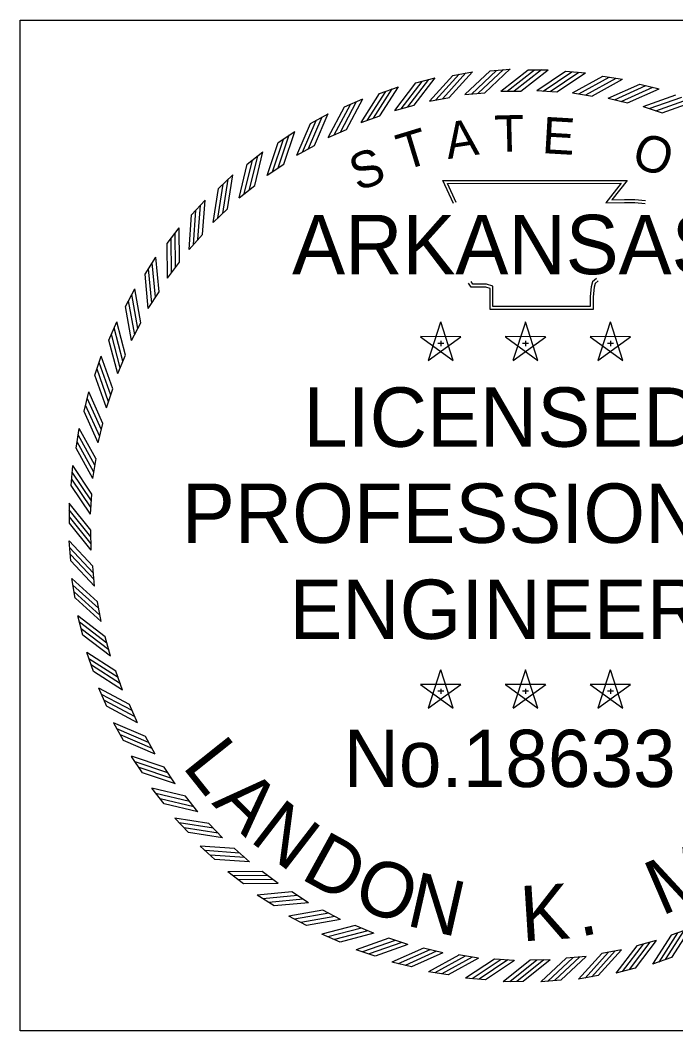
# Model space of a CAD drawing. Extents: x 0 to 1228740, y 0 to 152440.
# Drawn here: x 30.673 to 32.457, y 22.685 to 25.435 of the extents above; entities that cross this region are included whole.
import ezdxf

# ---------------------------------------------------------------- set-up
doc = ezdxf.new("R2010")
doc.units = 0
doc.layers.add('R_No Plot', color=7, linetype='Continuous')
doc.layers.add('STAMP_LKM', color=7, linetype='Continuous')

msp = doc.modelspace()

# ---------------------------------------------------------------- linework, layer by layer
at = {"layer": 'R_No Plot'}
msp.add_lwpolyline([(30.6731, 25.4352), (33.4231, 25.4352), (33.4231, 22.6852), (30.6731, 22.6852)], close=True, dxfattribs=at)
at = {"layer": 'STAMP_LKM'}
for p, q in [((31.952, 25.2973), (32.0062, 25.3023)), ((32.055, 25.3004), (32.1094, 25.3004)), ((31.7497, 25.2646), (31.8023, 25.2785)), ((31.8501, 25.2851), (31.9037, 25.2946)), ((32.1569, 25.2963), (32.2112, 25.2923)), ((32.2586, 25.2831), (32.3124, 25.2746)), ((31.6512, 25.2359), (31.7025, 25.254)), ((32.3589, 25.2615), (32.4118, 25.2486)), ((31.5555, 25.1991), (31.6051, 25.2214)), ((31.7871, 25.2152), (31.8408, 25.2247)), ((31.8834, 25.2329), (31.9377, 25.2379)), ((31.9808, 25.2425), (32.0353, 25.2425)), ((32.0786, 25.244), (32.133, 25.24)), ((32.1763, 25.2374), (32.2301, 25.2289)), ((32.2731, 25.2228), (32.326, 25.2099)), ((31.6926, 25.1897), (31.7453, 25.2036)), ((32.3683, 25.2003), (32.42, 25.183)), ((31.4631, 25.1545), (31.5107, 25.1808)), ((31.6005, 25.1565), (31.6519, 25.1747)), ((31.5115, 25.1158), (31.5612, 25.1382)), ((31.3747, 25.1024), (31.42, 25.1326)), ((31.4262, 25.0679), (31.4739, 25.0943)), ((31.291, 25.0433), (31.3336, 25.0771)), ((31.3451, 25.0131), (31.3904, 25.0433)), ((31.2124, 24.9774), (31.2521, 25.0146)), ((31.2688, 24.9518), (31.3115, 24.9857)), ((31.1395, 24.9052), (31.176, 24.9456)), ((31.1978, 24.8844), (31.2376, 24.9217)), ((31.0728, 24.8273), (31.1058, 24.8706)), ((31.1327, 24.8113), (31.1692, 24.8518)), ((31.0128, 24.7442), (31.0421, 24.79)), ((31.0738, 24.7332), (31.1068, 24.7765)), ((30.9598, 24.6563), (30.9853, 24.7044)), ((31.0215, 24.6504), (31.0509, 24.6963)), ((30.9143, 24.5644), (30.9357, 24.6144)), ((31.8172, 24.6139), (31.7832, 24.5095)), ((31.8512, 24.5095), (31.8173, 24.614)), ((32.048, 24.6139), (32.014, 24.5095)), ((32.0819, 24.5095), (32.0481, 24.614)), ((32.2788, 24.6139), (32.2448, 24.5095)), ((32.3127, 24.5095), (32.2789, 24.614)), ((30.9763, 24.5636), (31.0018, 24.6118)), ((31.8721, 24.574), (31.7623, 24.5741)), ((31.7624, 24.574), (31.8512, 24.5094)), ((31.7833, 24.5095), (31.8723, 24.574)), ((31.8174, 24.5623), (31.8174, 24.5486)), ((32.1029, 24.574), (31.9931, 24.5741)), ((31.9932, 24.574), (32.082, 24.5094)), ((32.0141, 24.5095), (32.103, 24.574)), ((32.0481, 24.5623), (32.0481, 24.5486)), ((32.3337, 24.574), (32.2238, 24.5741)), ((32.2239, 24.574), (32.3127, 24.5094)), ((32.2449, 24.5095), (32.3338, 24.574)), ((32.2789, 24.5623), (32.2789, 24.5486)), ((31.8094, 24.5565), (31.8258, 24.5565)), ((32.0402, 24.5565), (32.0565, 24.5565)), ((32.271, 24.5565), (32.2873, 24.5565)), ((30.8766, 24.4691), (30.8937, 24.5207)), ((30.9384, 24.4734), (30.9598, 24.5235)), ((30.8468, 24.3709), (30.8597, 24.4238)), ((30.908, 24.3803), (30.9253, 24.4321)), ((30.8855, 24.2851), (30.8984, 24.3381)), ((30.8252, 24.2706), (30.8337, 24.3244)), ((30.8709, 24.1883), (30.8794, 24.2422)), ((30.812, 24.1689), (30.816, 24.2232)), ((30.8643, 24.0906), (30.8683, 24.145)), ((30.8073, 24.0665), (30.8068, 24.1209)), ((30.8658, 23.9928), (30.8653, 24.0473)), ((30.811, 23.964), (30.806, 24.0182)), ((30.8754, 23.8954), (30.8704, 23.9497)), ((30.8231, 23.8622), (30.8137, 23.9157)), ((30.8931, 23.7991), (30.8836, 23.8528)), ((30.8437, 23.7617), (30.8298, 23.8143)), ((30.9186, 23.7046), (30.9047, 23.7573)), ((30.8724, 23.6632), (30.8543, 23.7145)), ((30.9518, 23.6125), (30.9336, 23.664)), ((31.8172, 23.6676), (31.7832, 23.5632)), ((31.8512, 23.5633), (31.8173, 23.6678)), ((32.048, 23.6676), (32.014, 23.5632)), ((32.0819, 23.5633), (32.0481, 23.6678)), ((32.2788, 23.6676), (32.2448, 23.5632)), ((32.3127, 23.5633), (32.2789, 23.6678)), ((31.8721, 23.6278), (31.7623, 23.6279)), ((31.7624, 23.6278), (31.8512, 23.5631)), ((31.7833, 23.5633), (31.8723, 23.6277)), ((32.1029, 23.6278), (31.9931, 23.6279)), ((31.9932, 23.6278), (32.082, 23.5631)), ((32.0141, 23.5633), (32.103, 23.6277)), ((32.3337, 23.6278), (32.2238, 23.6279)), ((32.2239, 23.6278), (32.3127, 23.5631)), ((32.2449, 23.5633), (32.3338, 23.6277)), ((30.9092, 23.5675), (30.8869, 23.6171)), ((31.8094, 23.6102), (31.8258, 23.6102)), ((31.8174, 23.6161), (31.8174, 23.6023)), ((32.0402, 23.6102), (32.0565, 23.6102)), ((32.0481, 23.6161), (32.0481, 23.6023)), ((32.271, 23.6102), (32.2873, 23.6102)), ((32.2789, 23.6161), (32.2789, 23.6023)), ((30.9925, 23.5235), (30.9701, 23.5733)), ((30.9538, 23.4751), (30.9275, 23.5227)), ((31.0404, 23.4382), (31.014, 23.4859)), ((31.0059, 23.3868), (30.9757, 23.432)), ((31.0952, 23.3571), (31.065, 23.4025)), ((31.065, 23.303), (31.0312, 23.3456)), ((31.1565, 23.2808), (31.1226, 23.3235)), ((31.1309, 23.2244), (31.0937, 23.2641)), ((31.2239, 23.2098), (31.1866, 23.2496)), ((31.2031, 23.1515), (31.1627, 23.188)), ((31.297, 23.1447), (31.2565, 23.1812)), ((31.281, 23.0848), (31.2377, 23.1178)), ((31.3751, 23.0858), (31.3318, 23.1189)), ((31.3641, 23.0248), (31.3183, 23.0541)), ((31.4579, 23.0335), (31.412, 23.0629)), ((31.452, 22.9719), (31.4039, 22.9973)), ((31.5447, 22.9883), (31.4965, 23.0138)), ((31.6349, 22.9504), (31.5848, 22.9718)), ((32.4958, 22.9638), (32.4443, 22.9456)), ((31.5439, 22.9263), (31.4939, 22.9477)), ((31.728, 22.92), (31.6762, 22.9373)), ((31.8232, 22.8975), (31.7702, 22.9104)), ((32.4037, 22.9306), (32.3509, 22.9167)), ((31.6392, 22.8886), (31.5876, 22.9058)), ((31.92, 22.8829), (31.8661, 22.8914)), ((32.0176, 22.8763), (31.9633, 22.8803)), ((32.2129, 22.8875), (32.1586, 22.8825)), ((32.3092, 22.9051), (32.2555, 22.8956)), ((32.4451, 22.8845), (32.3938, 22.8663)), ((31.7374, 22.8588), (31.6845, 22.8717)), ((32.1155, 22.8779), (32.061, 22.8774)), ((32.3466, 22.8557), (32.294, 22.8419)), ((31.8376, 22.8373), (31.7839, 22.8457)), ((31.9394, 22.824), (31.8851, 22.828)), ((32.2461, 22.8352), (32.1925, 22.8257)), ((32.0418, 22.8193), (31.9874, 22.8188)), ((32.1443, 22.823), (32.0901, 22.818))]:
    msp.add_line(p, q, dxfattribs=at)
for points in [[(31.9195, 25.2364), (31.9881, 25.3009)], [(31.9376, 25.2379), (32.0062, 25.3024)], [(31.9807, 25.2424), (32.0549, 25.3003)], [(31.9982, 25.2422), (32.0724, 25.3001)], [(32.0171, 25.2427), (32.0913, 25.3006)], [(32.0352, 25.2425), (32.1095, 25.3004)], [(31.7277, 25.1992), (31.7847, 25.2741)], [(31.7452, 25.2036), (31.8023, 25.2785)], [(31.787, 25.2152), (31.8501, 25.2851)], [(31.8043, 25.2181), (31.8673, 25.288)], [(31.8228, 25.2218), (31.8859, 25.2917)], [(31.8407, 25.2247), (31.9038, 25.2946)], [(31.8833, 25.2328), (31.9519, 25.2973)], [(31.9007, 25.2342), (31.9694, 25.2987)], [(32.0785, 25.2439), (32.1568, 25.2962)], [(32.096, 25.2425), (32.1743, 25.2948)], [(32.1149, 25.2415), (32.1932, 25.2938)], [(32.1329, 25.24), (32.2112, 25.2923)], [(32.1762, 25.2374), (32.2585, 25.283)], [(32.1935, 25.2345), (32.2758, 25.2801)], [(32.2122, 25.232), (32.2945, 25.2776)], [(32.2301, 25.229), (32.3124, 25.2746)], [(31.6347, 25.1688), (31.6854, 25.2482)], [(31.6519, 25.1747), (31.7025, 25.254)], [(31.6925, 25.1897), (31.7496, 25.2645)], [(31.7095, 25.194), (31.7666, 25.2688)], [(32.273, 25.2228), (32.3588, 25.2615)], [(32.29, 25.2185), (32.3758, 25.2572)], [(32.3084, 25.2144), (32.3942, 25.2531)], [(32.326, 25.21), (32.4118, 25.2487)], [(31.5612, 25.1382), (31.6051, 25.2214)], [(31.6005, 25.1564), (31.6512, 25.2358)], [(31.617, 25.1621), (31.6677, 25.2415)], [(32.3682, 25.2002), (32.4569, 25.2317)], [(32.3848, 25.1946), (32.4735, 25.226)], [(32.4028, 25.189), (32.4916, 25.2205)], [(31.5115, 25.1157), (31.5554, 25.199)], [(31.5275, 25.1228), (31.5715, 25.206)], [(31.5446, 25.1309), (31.5885, 25.2141)], [(32.42, 25.1831), (32.5087, 25.2146)], [(31.4415, 25.0761), (31.4785, 25.1627)], [(31.4579, 25.0857), (31.4948, 25.1723)], [(31.4738, 25.0943), (31.5107, 25.1809)], [(31.4261, 25.0678), (31.4631, 25.1544)], [(31.3597, 25.0226), (31.3894, 25.1119)], [(31.3752, 25.0334), (31.4049, 25.1228)], [(31.3904, 25.0433), (31.42, 25.1327)], [(31.345, 25.013), (31.3747, 25.1024)], [(31.2826, 24.9624), (31.3048, 25.0539)], [(31.2971, 24.9745), (31.3193, 25.066)], [(31.3114, 24.9857), (31.3336, 25.0771)], [(31.2688, 24.9517), (31.2909, 25.0432)], [(31.2242, 24.9094), (31.2387, 25.0024)], [(31.2375, 24.9217), (31.2521, 25.0147)], [(31.8523, 24.9362), (31.8233, 24.999), (32.3251, 24.9993), (32.2832, 24.9466), (32.3172, 24.9471), (32.3457, 24.9474), (32.3742, 24.9443)], [(31.1978, 24.8843), (31.2123, 24.9773)], [(31.2107, 24.8961), (31.2252, 24.9892)], [(31.8595, 24.9395), (31.8357, 24.9911), (32.3086, 24.9914), (32.2665, 24.9385), (32.3173, 24.9391), (32.3453, 24.9395), (32.3733, 24.9364)], [(31.1691, 24.8518), (31.176, 24.9457)], [(31.1445, 24.8241), (31.1513, 24.918)], [(31.1569, 24.8384), (31.1637, 24.9323)], [(31.1326, 24.8113), (31.1395, 24.9051)], [(31.1068, 24.7765), (31.1058, 24.8706)], [(31.0845, 24.7469), (31.0835, 24.841)], [(31.0956, 24.7622), (31.0947, 24.8563)], [(31.0738, 24.7331), (31.0728, 24.8272)], [(31.0508, 24.6963), (31.0421, 24.79)], [(31.0311, 24.665), (31.0224, 24.7587)], [(31.0409, 24.6811), (31.0322, 24.7749)], [(31.0215, 24.6503), (31.0128, 24.7441)], [(32.246, 24.7259), (32.2375, 24.719), (32.2346, 24.7086), (32.2318, 24.6825), (32.2318, 24.6479), (31.9517, 24.6479), (31.9517, 24.6947), (31.9517, 24.7051), (31.9403, 24.7086), (31.9005, 24.7086), (31.8934, 24.7194)], [(32.241, 24.7321), (32.2305, 24.7235), (32.2268, 24.71), (32.2238, 24.683), (32.2238, 24.6558), (31.9596, 24.6558), (31.9596, 24.6947), (31.9596, 24.711), (31.9415, 24.7165), (31.9047, 24.7165), (31.9, 24.7237)], [(31.0017, 24.6118), (30.9853, 24.7045)], [(30.9846, 24.5789), (30.9682, 24.6716)], [(30.9931, 24.5958), (30.9766, 24.6885)], [(30.9763, 24.5635), (30.9598, 24.6562)], [(30.9597, 24.5235), (30.9357, 24.6145)], [(30.9525, 24.5069), (30.9284, 24.5979)], [(30.9384, 24.4733), (30.9143, 24.5643)], [(30.9454, 24.4893), (30.9214, 24.5804)], [(30.9193, 24.4149), (30.8878, 24.5036)], [(30.9252, 24.432), (30.8937, 24.5207)], [(30.9137, 24.3968), (30.8823, 24.4855)], [(30.908, 24.3802), (30.8766, 24.469)], [(30.8983, 24.338), (30.8596, 24.4238)], [(30.8939, 24.3204), (30.8552, 24.4063)], [(30.8855, 24.285), (30.8468, 24.3708)], [(30.8898, 24.302), (30.8511, 24.3878)], [(30.8793, 24.2421), (30.8337, 24.3244)], [(30.8738, 24.2055), (30.8281, 24.2878)], [(30.8763, 24.2242), (30.8307, 24.3066)], [(30.8709, 24.1882), (30.8253, 24.2706)], [(30.8668, 24.1269), (30.8145, 24.2052)], [(30.8683, 24.145), (30.816, 24.2233)], [(30.8658, 24.108), (30.8135, 24.1863)], [(30.8644, 24.0906), (30.8121, 24.1689)], [(30.8653, 24.0472), (30.8067, 24.1209)], [(30.8653, 24.0291), (30.8067, 24.1028)], [(30.8659, 24.0102), (30.8073, 24.0839)], [(30.8659, 23.9927), (30.8073, 24.0664)], [(30.8704, 23.9496), (30.8059, 24.0182)], [(30.8719, 23.9316), (30.8074, 24.0002)], [(30.8741, 23.9128), (30.8096, 23.9814)], [(30.8755, 23.8953), (30.811, 23.9639)], [(30.8836, 23.8527), (30.8136, 23.9158)], [(30.8865, 23.8349), (30.8166, 23.8979)], [(30.8902, 23.8163), (30.8203, 23.8794)], [(30.8931, 23.799), (30.8232, 23.8621)], [(30.9047, 23.7573), (30.8298, 23.8143)], [(30.9091, 23.7397), (30.8342, 23.7968)], [(30.9143, 23.7215), (30.8394, 23.7786)], [(30.9186, 23.7046), (30.8437, 23.7616)], [(30.9336, 23.6639), (30.8542, 23.7146)], [(30.9395, 23.6467), (30.8601, 23.6974)], [(30.9462, 23.6291), (30.8668, 23.6797)], [(30.9518, 23.6125), (30.8725, 23.6632)], [(30.9701, 23.5732), (30.8869, 23.6172)], [(30.9774, 23.5566), (30.8941, 23.6006)], [(30.9855, 23.5395), (30.9023, 23.5835)], [(30.9926, 23.5235), (30.9093, 23.5675)], [(31.014, 23.4858), (30.9274, 23.5228)], [(31.0226, 23.4699), (30.936, 23.5068)], [(31.0321, 23.4536), (30.9456, 23.4905)], [(31.0405, 23.4382), (30.9539, 23.4751)], [(31.065, 23.4024), (30.9756, 23.4321)], [(31.0749, 23.3872), (30.9855, 23.4169)], [(31.0857, 23.3717), (30.9964, 23.4014)], [(31.0953, 23.3571), (31.0059, 23.3867)], [(31.1226, 23.3235), (31.0311, 23.3456)], [(31.1338, 23.3092), (31.0423, 23.3313)], [(31.1458, 23.2946), (31.0544, 23.3168)], [(31.1566, 23.2808), (31.0651, 23.303)], [(31.1866, 23.2495), (31.0936, 23.2641)], [(31.1989, 23.2362), (31.1059, 23.2508)], [(31.2121, 23.2227), (31.1191, 23.2373)], [(31.224, 23.2098), (31.131, 23.2244)], [(31.2565, 23.1812), (31.1626, 23.188)], [(31.2699, 23.1689), (31.176, 23.1757)], [(31.2842, 23.1565), (31.1903, 23.1634)], [(31.297, 23.1447), (31.2031, 23.1515)], [(31.3318, 23.1188), (31.2377, 23.1178)], [(31.3461, 23.1077), (31.252, 23.1067)], [(31.3614, 23.0965), (31.2673, 23.0956)], [(31.3752, 23.0858), (31.2811, 23.0848)], [(31.412, 23.0629), (31.3183, 23.0541)], [(31.4272, 23.053), (31.3334, 23.0442)], [(31.4433, 23.0431), (31.3496, 23.0344)], [(31.458, 23.0335), (31.3642, 23.0248)], [(31.4965, 23.0137), (31.4038, 22.9973)], [(31.5125, 23.0051), (31.4198, 22.9887)], [(31.5294, 22.9966), (31.4367, 22.9802)], [(31.5448, 22.9883), (31.4521, 22.9719)], [(31.5848, 22.9718), (31.4938, 22.9477)], [(31.6014, 22.9645), (31.5104, 22.9404)], [(32.4958, 22.9639), (32.4451, 22.8845)], [(31.619, 22.9574), (31.5279, 22.9334)], [(31.635, 22.9504), (31.544, 22.9264)], [(31.6763, 22.9372), (31.5876, 22.9057)], [(32.4444, 22.9456), (32.3937, 22.8663)], [(32.4616, 22.9515), (32.4109, 22.8722)], [(32.4792, 22.9582), (32.4285, 22.8789)], [(31.6934, 22.9313), (31.6047, 22.8999)], [(31.7115, 22.9258), (31.6228, 22.8943)], [(31.728, 22.9201), (31.6393, 22.8886)], [(31.7703, 22.9103), (31.6845, 22.8717)], [(32.351, 22.9167), (32.294, 22.8418)], [(32.3686, 22.9211), (32.3115, 22.8463)], [(32.3868, 22.9263), (32.3297, 22.8515)], [(32.4037, 22.9306), (32.3467, 22.8558)], [(31.7879, 22.9059), (31.702, 22.8672)], [(31.8063, 22.9018), (31.7205, 22.8631)], [(31.8233, 22.8975), (31.7375, 22.8588)], [(31.8662, 22.8913), (31.7838, 22.8457)], [(31.8841, 22.8883), (31.8017, 22.8427)], [(31.9028, 22.8858), (31.8205, 22.8402)], [(31.9201, 22.8829), (31.8377, 22.8373)], [(31.9633, 22.8803), (31.885, 22.828)], [(32.1587, 22.8824), (32.0901, 22.818)], [(32.1767, 22.8839), (32.1081, 22.8195)], [(32.1955, 22.8861), (32.1269, 22.8216)], [(32.213, 22.8875), (32.1444, 22.8231)], [(32.2556, 22.8956), (32.1925, 22.8257)], [(32.2734, 22.8986), (32.2104, 22.8287)], [(32.292, 22.9023), (32.2289, 22.8323)], [(32.3092, 22.9051), (32.2462, 22.8352)], [(31.9814, 22.8788), (31.9031, 22.8265)], [(32.0003, 22.8778), (31.922, 22.8255)], [(32.0177, 22.8764), (31.9394, 22.8241)], [(32.061, 22.8773), (31.9873, 22.8187)], [(32.0792, 22.8773), (32.0055, 22.8187)], [(32.0981, 22.8779), (32.0244, 22.8193)], [(32.1156, 22.8779), (32.0419, 22.8193)]]:
    msp.add_lwpolyline(points, dxfattribs=at)

# ---------------------------------------------------------------- texts
for s, height, rotation, p in [('A', 0.099, 8.6788, (31.837, 25.057)), ('T', 0.099, 1.4789, (31.9648, 25.0767)), ('E', 0.099, 356.672, (32.0915, 25.0737)), ('T', 0.099, 16.9015, (31.7168, 25.0256)), ('O', 0.099, 341.2218, (32.3318, 25.0398)), ('S', 0.099, 19.7726, (31.591, 24.9691)), ('L', 0.1504, 308.5467, (31.1117, 23.4045)), ('A', 0.1504, 315.1131, (31.1922, 23.3035)), ('N', 0.1504, 322.4091, (31.2944, 23.203)), ('D', 0.1504, 331.1643, (31.4327, 23.1007)), ('M', 0.1504, 23.3308, (32.4179, 22.9966)), ('O', 0.1504, 339.1899, (31.5718, 23.0264)), ('N', 0.1504, 347.2155, (31.7199, 22.9723)), ('K', 0.1504, 3.6315, (32.0385, 22.9283)), ('.', 0.1504, 11.6571, (32.1958, 22.9403))]:
    msp.add_text(s, height=height, rotation=rotation, dxfattribs=at).set_placement(p)
for s, height, p in [('ARKANSAS', 0.16155, (31.4131, 24.744)), ('LICENSED', 0.16155, (31.4439, 24.2744)), ('PROFESSIONAL', 0.161547, (31.1131, 24.0129)), ('ENGINEER', 0.16155, (31.4054, 23.7513)), ('No.18633', 0.15578, (31.5531, 23.3485))]:
    msp.add_text(s, height=height, dxfattribs=at).set_placement(p)

doc.saveas('drawing.dxf')
